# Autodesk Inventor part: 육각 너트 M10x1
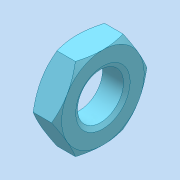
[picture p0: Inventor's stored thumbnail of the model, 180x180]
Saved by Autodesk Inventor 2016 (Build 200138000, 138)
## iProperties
Created: 2024-09
Part Number: 육각 너트 M10x1
Material: 일반
Description: 6각 너트 및 6각 가는 너트 - 이중 모따기
Document SubType Name: Modeling
Designer: pc-7
Density: 1 g/cm^3
Appearance: 기본값
Author: jhkim
Sending System: Autodesk Inventor 2025
Preprocessor: ST-DEVELOPER v20
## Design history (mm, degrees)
node "육각 너트 M10x11"
node "솔리드1"
body "Solid1"
